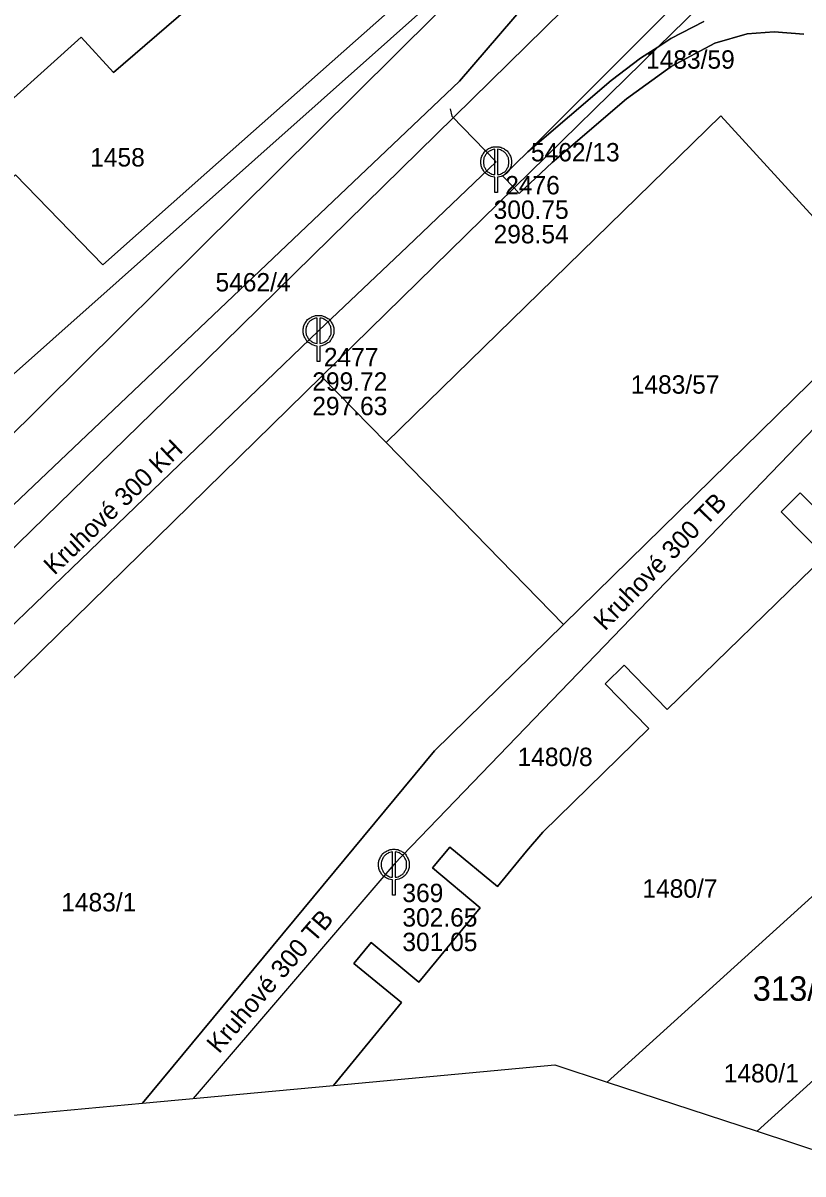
# Model space of a CAD drawing. Extents: x -570890 to -570546, y -1086481 to -1086296.
# Drawn here: x -570803.2 to -570739.5, y -1086468.4 to -1086374.4 of the extents above; entities that cross this region are included whole.
import ezdxf

# ---------------------------------------------------------------- set-up
doc = ezdxf.new("R2010")
doc.units = 0
for name, color, linetype in [('Adresní místo-text', 7, 'Continuous'), ('Default', 7, 'Continuous'), ('Kanalizační stoka', 7, 'Continuous'), ('Kanalizační šachta', 7, 'Continuous'), ('Parcela-polygon', 7, 'Continuous'), ('Parcela-text', 7, 'Continuous'), ('Popis kmenové stoky', 7, 'Continuous'), ('Popis šachty', 7, 'Continuous')]:
    doc.layers.add(name, color=color, linetype=linetype)

msp = doc.modelspace()

# ---------------------------------------------------------------- linework, layer by layer
at = {"layer": 'Default'}
for points in [[(-570764.653, -1086386.998), (-570764.911, -1086386.98), (-570765.173, -1086386.834), (-570765.47, -1086386.67), (-570765.635, -1086386.373), (-570765.8, -1086386.075), (-570765.8, -1086385.75), (-570765.8, -1086385.423), (-570765.632, -1086385.123), (-570765.463, -1086384.822), (-570765.165, -1086384.661), (-570764.867, -1086384.5), (-570764.55, -1086384.5), (-570764.235, -1086384.5), (-570763.936, -1086384.661), (-570763.637, -1086384.822), (-570763.468, -1086385.123), (-570763.3, -1086385.423), (-570763.3, -1086385.75), (-570763.3, -1086386.075), (-570763.465, -1086386.373), (-570763.63, -1086386.67), (-570763.927, -1086386.834), (-570764.189, -1086386.98), (-570764.447, -1086386.998)], [(-570764.653, -1086384.712), (-570764.85, -1086384.729), (-570765.065, -1086384.844), (-570765.314, -1086384.979), (-570765.453, -1086385.229), (-570765.592, -1086385.479), (-570765.592, -1086385.75), (-570765.592, -1086386.021), (-570765.456, -1086386.268), (-570765.319, -1086386.514), (-570765.07, -1086386.651), (-570764.858, -1086386.771), (-570764.653, -1086386.785)], [(-570764.447, -1086386.785), (-570764.242, -1086386.771), (-570764.028, -1086386.651), (-570763.781, -1086386.514), (-570763.644, -1086386.268), (-570763.508, -1086386.021), (-570763.508, -1086385.75), (-570763.508, -1086385.479), (-570763.648, -1086385.229), (-570763.788, -1086384.979), (-570764.037, -1086384.844), (-570764.25, -1086384.729), (-570764.447, -1086384.712)], [(-570779.173, -1086400.778), (-570779.431, -1086400.76), (-570779.693, -1086400.614), (-570779.99, -1086400.45), (-570780.155, -1086400.153), (-570780.32, -1086399.855), (-570780.32, -1086399.53), (-570780.32, -1086399.203), (-570780.152, -1086398.903), (-570779.983, -1086398.602), (-570779.685, -1086398.441), (-570779.387, -1086398.28), (-570779.07, -1086398.28), (-570778.755, -1086398.28), (-570778.456, -1086398.441), (-570778.157, -1086398.602), (-570777.988, -1086398.903), (-570777.82, -1086399.203), (-570777.82, -1086399.53), (-570777.82, -1086399.855), (-570777.985, -1086400.153), (-570778.15, -1086400.45), (-570778.447, -1086400.614), (-570778.709, -1086400.76), (-570778.967, -1086400.778)], [(-570779.173, -1086398.492), (-570779.37, -1086398.509), (-570779.585, -1086398.624), (-570779.834, -1086398.759), (-570779.973, -1086399.009), (-570780.112, -1086399.259), (-570780.112, -1086399.53), (-570780.112, -1086399.801), (-570779.976, -1086400.048), (-570779.839, -1086400.294), (-570779.59, -1086400.431), (-570779.378, -1086400.551), (-570779.173, -1086400.565)], [(-570778.967, -1086400.565), (-570778.762, -1086400.551), (-570778.548, -1086400.431), (-570778.301, -1086400.294), (-570778.164, -1086400.048), (-570778.028, -1086399.801), (-570778.028, -1086399.53), (-570778.028, -1086399.259), (-570778.168, -1086399.009), (-570778.308, -1086398.759), (-570778.557, -1086398.624), (-570778.77, -1086398.509), (-570778.967, -1086398.492)], [(-570773.013, -1086444.378), (-570773.271, -1086444.36), (-570773.533, -1086444.214), (-570773.83, -1086444.05), (-570773.995, -1086443.753), (-570774.16, -1086443.455), (-570774.16, -1086443.13), (-570774.16, -1086442.803), (-570773.992, -1086442.503), (-570773.823, -1086442.202), (-570773.525, -1086442.041), (-570773.227, -1086441.88), (-570772.91, -1086441.88), (-570772.595, -1086441.88), (-570772.296, -1086442.041), (-570771.997, -1086442.202), (-570771.828, -1086442.503), (-570771.66, -1086442.803), (-570771.66, -1086443.13), (-570771.66, -1086443.455), (-570771.825, -1086443.753), (-570771.99, -1086444.05), (-570772.287, -1086444.214), (-570772.549, -1086444.36), (-570772.807, -1086444.378)], [(-570773.013, -1086442.092), (-570773.21, -1086442.109), (-570773.425, -1086442.224), (-570773.674, -1086442.359), (-570773.813, -1086442.609), (-570773.952, -1086442.859), (-570773.952, -1086443.13), (-570773.952, -1086443.401), (-570773.816, -1086443.648), (-570773.679, -1086443.894), (-570773.43, -1086444.031), (-570773.218, -1086444.151), (-570773.013, -1086444.165)], [(-570772.807, -1086444.165), (-570772.602, -1086444.151), (-570772.388, -1086444.031), (-570772.141, -1086443.894), (-570772.004, -1086443.648), (-570771.868, -1086443.401), (-570771.868, -1086443.13), (-570771.868, -1086442.859), (-570772.008, -1086442.609), (-570772.148, -1086442.359), (-570772.397, -1086442.224), (-570772.61, -1086442.109), (-570772.807, -1086442.092)]]:
    msp.add_open_spline(points, degree=3, dxfattribs=at)
at = {"layer": 'Kanalizační stoka'}
for p, q in [((-570737.78, -1086406.68), (-570772.91, -1086443.13)), ((-570772.91, -1086443.13), (-570789.312, -1086462.228))]:
    msp.add_line(p, q, dxfattribs=at)
for points in [[(-570768.32, -1086381.42), (-570768.185, -1086382.02), (-570764.55, -1086385.75)], [(-570764.55, -1086385.75), (-570771.81, -1086392.64), (-570779.07, -1086399.53)], [(-570779.07, -1086399.53), (-570794.035, -1086413.905), (-570809, -1086428.28)]]:
    msp.add_lwpolyline(points, dxfattribs=at)
at = {"layer": 'Kanalizační šachta'}
for points in [[(-570764.653, -1086386.785), (-570764.653, -1086384.712)], [(-570764.447, -1086384.712), (-570764.447, -1086386.785)], [(-570764.447, -1086386.998), (-570764.447, -1086388.25), (-570764.653, -1086388.25), (-570764.653, -1086386.998)], [(-570779.173, -1086400.565), (-570779.173, -1086398.492)], [(-570778.967, -1086398.492), (-570778.967, -1086400.565)], [(-570778.967, -1086400.778), (-570778.967, -1086402.03), (-570779.173, -1086402.03), (-570779.173, -1086400.778)], [(-570773.013, -1086444.165), (-570773.013, -1086442.092)], [(-570772.807, -1086442.092), (-570772.807, -1086444.165)], [(-570772.807, -1086444.378), (-570772.807, -1086445.63), (-570773.013, -1086445.63), (-570773.013, -1086444.378)]]:
    msp.add_lwpolyline(points, dxfattribs=at)
at = {"layer": 'Parcela-polygon'}
for p, q in [((-570793.457, -1086462.612), (-570777.84, -1086461.163)), ((-570755.467, -1086460.887), (-570743.23, -1086464.907)), ((-570743.23, -1086464.907), (-570732.62, -1086468.393))]:
    msp.add_line(p, q, dxfattribs=at)
for points in [[(-570834.086, -1086429.769), (-570756.68, -1086361), (-570756.34, -1086360.67), (-570756.02, -1086355.74), (-570754.01, -1086353.82), (-570801.51, -1086303.97), (-570828.93, -1086331.81), (-570842.37, -1086345.54), (-570846.35, -1086350.15), (-570843.03, -1086353.56), (-570850.23, -1086360.64), (-570848.15, -1086362.79), (-570862.71, -1086376.95), (-570857.62, -1086382.09), (-570857.78, -1086382.29), (-570851.41, -1086388.5), (-570856.93, -1086394.12), (-570873.87, -1086376.88), (-570874.636, -1086377.574)], [(-570704.56, -1086305.593), (-570706.17, -1086307.5), (-570707.16, -1086308.58), (-570707.13, -1086309.53), (-570707.29, -1086311.56), (-570707.81, -1086313.54), (-570709.31, -1086316.22), (-570714.9, -1086323.38), (-570723.45, -1086333.39), (-570738.16, -1086351.15), (-570747.27, -1086361.72), (-570767.99, -1086382.05), (-570788.27, -1086401.95), (-570809.12, -1086422.25), (-570826.603, -1086439.399)], [(-570821.918, -1086445.43), (-570778.82, -1086403.26), (-570763.09, -1086387.87), (-570764.01, -1086386.9), (-570761.96, -1086384.93), (-570742.89, -1086365.83), (-570730.22, -1086351.07), (-570727.69, -1086353.18), (-570725.54, -1086350.6), (-570715.91, -1086339.05), (-570710.14, -1086332.11), (-570695.97, -1086315.11), (-570689.451, -1086307.511)], [(-570826.603, -1086439.399), (-570809.12, -1086422.25), (-570788.27, -1086401.95), (-570767.99, -1086382.05), (-570747.27, -1086361.72), (-570738.16, -1086351.15), (-570723.45, -1086333.39), (-570714.9, -1086323.38), (-570709.31, -1086316.22), (-570707.81, -1086313.54), (-570707.29, -1086311.56), (-570707.13, -1086309.53), (-570707.16, -1086308.58), (-570740.99, -1086345.46), (-570751.79, -1086356.16), (-570752.3, -1086356.66), (-570750.1, -1086358.88), (-570767.56, -1086379.15), (-570828.488, -1086436.973)], [(-570789.21, -1086333.9), (-570781.72, -1086326.7), (-570771.31, -1086337.28), (-570771.53, -1086337.5), (-570761.89, -1086347.32), (-570755.87, -1086353.47), (-570761.86, -1086359.31), (-570773.1, -1086370.2), (-570771.53, -1086371.82), (-570788.19, -1086386.62), (-570796.69, -1086394.15), (-570803.85, -1086386.79), (-570812.78, -1086394.83), (-570816.48, -1086390.61), (-570807.55, -1086382.66), (-570807.02, -1086383.24), (-570798.47, -1086375.55), (-570795.84, -1086378.45), (-570779.1, -1086364.02), (-570769.21, -1086354.43), (-570789.21, -1086333.9)], [(-570828.488, -1086436.973), (-570767.56, -1086379.15), (-570750.1, -1086358.88), (-570752.3, -1086356.66), (-570756.34, -1086360.67), (-570756.68, -1086361), (-570830.617, -1086434.233)], [(-570830.617, -1086434.233), (-570756.68, -1086361), (-570834.086, -1086429.769)], [(-570741.24, -1086366.49), (-570751.33, -1086376.36), (-570750.27, -1086375.67), (-570747.58, -1086374.29)], [(-570747.58, -1086374.29), (-570750.27, -1086375.67), (-570751.33, -1086376.36), (-570763.09, -1086387.87), (-570762.66, -1086388.33), (-570759.98, -1086385.79), (-570753.91, -1086380.6), (-570750.25, -1086377.96), (-570746.68, -1086376.04), (-570744.03, -1086375.29), (-570741.82, -1086375.11), (-570739.4, -1086375.3)], [(-570739.4, -1086375.3), (-570741.82, -1086375.11), (-570744.03, -1086375.29), (-570746.68, -1086376.04), (-570750.25, -1086377.96), (-570753.91, -1086380.6), (-570759.98, -1086385.79), (-570762.66, -1086388.33), (-570763.09, -1086387.87), (-570778.82, -1086403.26), (-570773.55, -1086408.66), (-570746.18, -1086381.97), (-570732.22, -1086397.24)], [(-570732.22, -1086397.24), (-570759.06, -1086423.52), (-570769.59, -1086433.84), (-570793.457, -1086462.612)], [(-570793.457, -1086462.612), (-570769.59, -1086433.84), (-570759.06, -1086423.52), (-570773.55, -1086408.66), (-570778.82, -1086403.26), (-570821.918, -1086445.43)], [(-570736.12, -1086416.4), (-570739.69, -1086412.77), (-570741.25, -1086414.31), (-570737.7, -1086417.95), (-570750.57, -1086430.47), (-570754.08, -1086426.83), (-570755.63, -1086428.37), (-570752.08, -1086432), (-570760.75, -1086440.49), (-570762.06, -1086442.02), (-570764.44, -1086444.92), (-570768.34, -1086441.71), (-570769.76, -1086443.4), (-570765.87, -1086446.65), (-570770.86, -1086452.73), (-570774.78, -1086449.5), (-570776.19, -1086451.21), (-570772.28, -1086454.4), (-570777.84, -1086461.163)], [(-570777.84, -1086461.163), (-570772.28, -1086454.4), (-570776.19, -1086451.21), (-570774.78, -1086449.5), (-570770.86, -1086452.73), (-570765.87, -1086446.65), (-570769.76, -1086443.4), (-570768.34, -1086441.71), (-570764.44, -1086444.92), (-570762.06, -1086442.02), (-570760.75, -1086440.49), (-570752.08, -1086432), (-570755.63, -1086428.37), (-570754.08, -1086426.83), (-570750.57, -1086430.47), (-570737.7, -1086417.95), (-570741.25, -1086414.31), (-570739.69, -1086412.77), (-570736.12, -1086416.4)], [(-570743.23, -1086464.907), (-570737.15, -1086459.41), (-570735.94, -1086460.74), (-570733.16, -1086458.23), (-570734.37, -1086456.9), (-570727.85, -1086451.01), (-570729.02, -1086449.73), (-570722.36, -1086443.72), (-570721.15, -1086445.06), (-570718.33, -1086442.51), (-570719.54, -1086441.17), (-570706.72, -1086429.59), (-570705.51, -1086430.93), (-570702.69, -1086428.39), (-570703.9, -1086427.05), (-570697.39, -1086421.17), (-570704.98, -1086412.95), (-570736.47, -1086441.32), (-570735.28, -1086442.64), (-570755.467, -1086460.887)], [(-570755.467, -1086460.887), (-570735.28, -1086442.64), (-570736.47, -1086441.32), (-570704.98, -1086412.95), (-570697.39, -1086421.17), (-570703.9, -1086427.05), (-570702.69, -1086428.39), (-570705.51, -1086430.93), (-570706.72, -1086429.59), (-570719.54, -1086441.17), (-570718.33, -1086442.51), (-570721.15, -1086445.06), (-570722.36, -1086443.72), (-570729.02, -1086449.73), (-570727.85, -1086451.01), (-570734.37, -1086456.9), (-570733.16, -1086458.23), (-570735.94, -1086460.74), (-570737.15, -1086459.41), (-570743.23, -1086464.907)], [(-570821.918, -1086445.43), (-570807.552, -1086463.921), (-570793.457, -1086462.612)], [(-570777.84, -1086461.163), (-570759.743, -1086459.483), (-570755.467, -1086460.887)]]:
    msp.add_lwpolyline(points, dxfattribs=at)
for points in [[(-570733.22, -1086359.47), (-570733.55, -1086358.32), (-570733.38, -1086356.66), (-570732.74, -1086354.97), (-570731.68, -1086353.29), (-570730.22, -1086351.07), (-570742.89, -1086365.83), (-570761.96, -1086384.93), (-570755.16, -1086379.1), (-570752.74, -1086377.28), (-570751.33, -1086376.36), (-570741.24, -1086366.49)], [(-570795.84, -1086378.45), (-570798.47, -1086375.55), (-570807.02, -1086383.24), (-570807.55, -1086382.66), (-570816.48, -1086390.61), (-570812.78, -1086394.83), (-570803.85, -1086386.79), (-570796.69, -1086394.15), (-570788.19, -1086386.62), (-570771.53, -1086371.82), (-570773.1, -1086370.2), (-570779.1, -1086364.02)], [(-570764.01, -1086386.9), (-570763.09, -1086387.87), (-570751.33, -1086376.36), (-570752.74, -1086377.28), (-570755.16, -1086379.1), (-570761.96, -1086384.93)], [(-570773.55, -1086408.66), (-570759.06, -1086423.52), (-570732.22, -1086397.24), (-570746.18, -1086381.97)]]:
    msp.add_lwpolyline(points, close=True, dxfattribs=at)

# ---------------------------------------------------------------- texts
at = {"layer": 'Adresní místo-text'}
msp.add_text('313/11', height=2, dxfattribs=at).set_placement((-570743.581, -1086454.25))
at = {"layer": 'Parcela-text'}
for s, p in [('1483/59', (-570752.3, -1086378.13)), ('5462/13', (-570761.71, -1086385.7)), ('1458', (-570797.73, -1086386.12)), ('5462/4', (-570787.49, -1086396.32)), ('1483/57', (-570753.55, -1086404.67)), ('1480/8', (-570762.8, -1086435.08)), ('1480/7', (-570752.6, -1086445.83)), ('1483/1', (-570800.1, -1086446.95)), ('1480/1', (-570745.95, -1086460.91))]:
    msp.add_text(s, height=1.5, dxfattribs=at).set_placement(p)
at = {"layer": 'Popis kmenové stoky'}
for s, rotation, p in [('Kruhové 300 KH', 43.84799, (-570800.66, -1086419.549)), ('Kruhové 300 TB', 46.05647, (-570755.659, -1086424.1)), ('Kruhové 300 TB', 49.34278, (-570787.205, -1086458.631))]:
    msp.add_text(s, height=1.5, rotation=rotation, dxfattribs=at).set_placement(p)
at = {"layer": 'Popis šachty'}
for s, p in [('2476', (-570763.809, -1086388.393)), ('300.75', (-570764.759, -1086390.393)), ('298.54', (-570764.759, -1086392.393)), ('2477', (-570778.63, -1086402.427)), ('299.72', (-570779.579, -1086404.427)), ('297.63', (-570779.579, -1086406.427)), ('369', (-570772.216, -1086446.192)), ('302.65', (-570772.216, -1086448.192)), ('301.05', (-570772.216, -1086450.192))]:
    msp.add_text(s, height=1.5, dxfattribs=at).set_placement(p)

doc.saveas('drawing.dxf')
